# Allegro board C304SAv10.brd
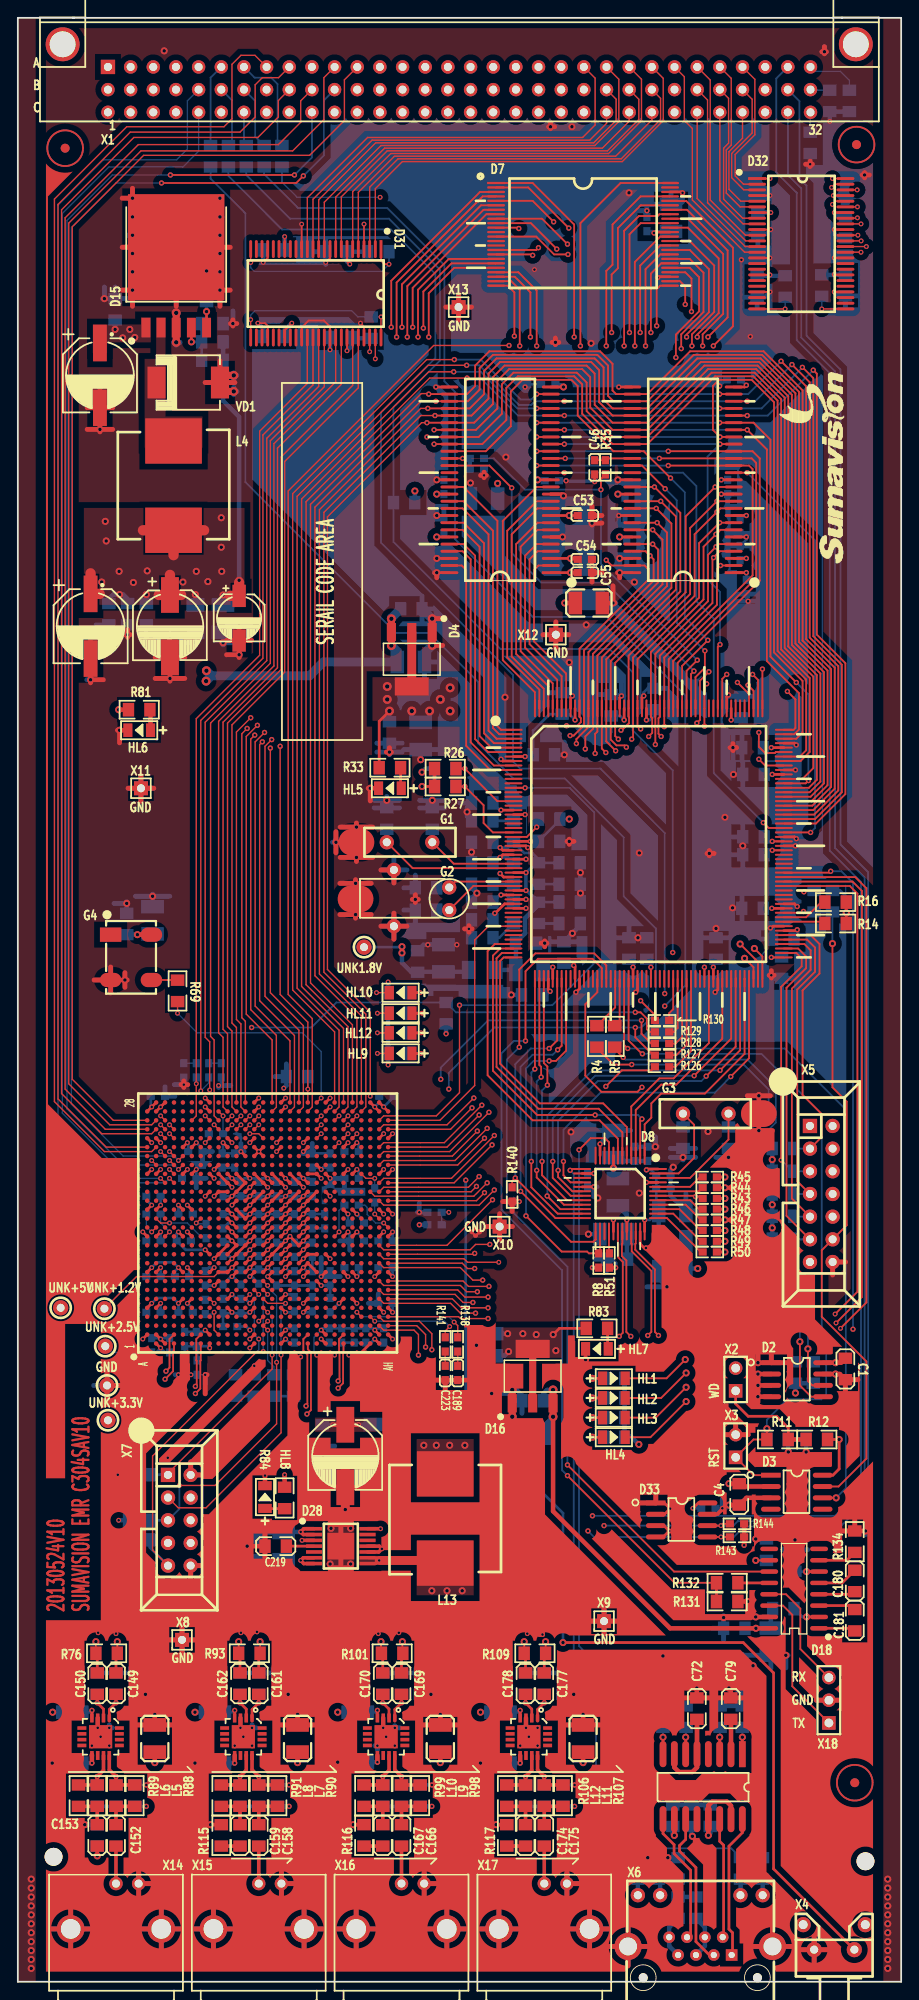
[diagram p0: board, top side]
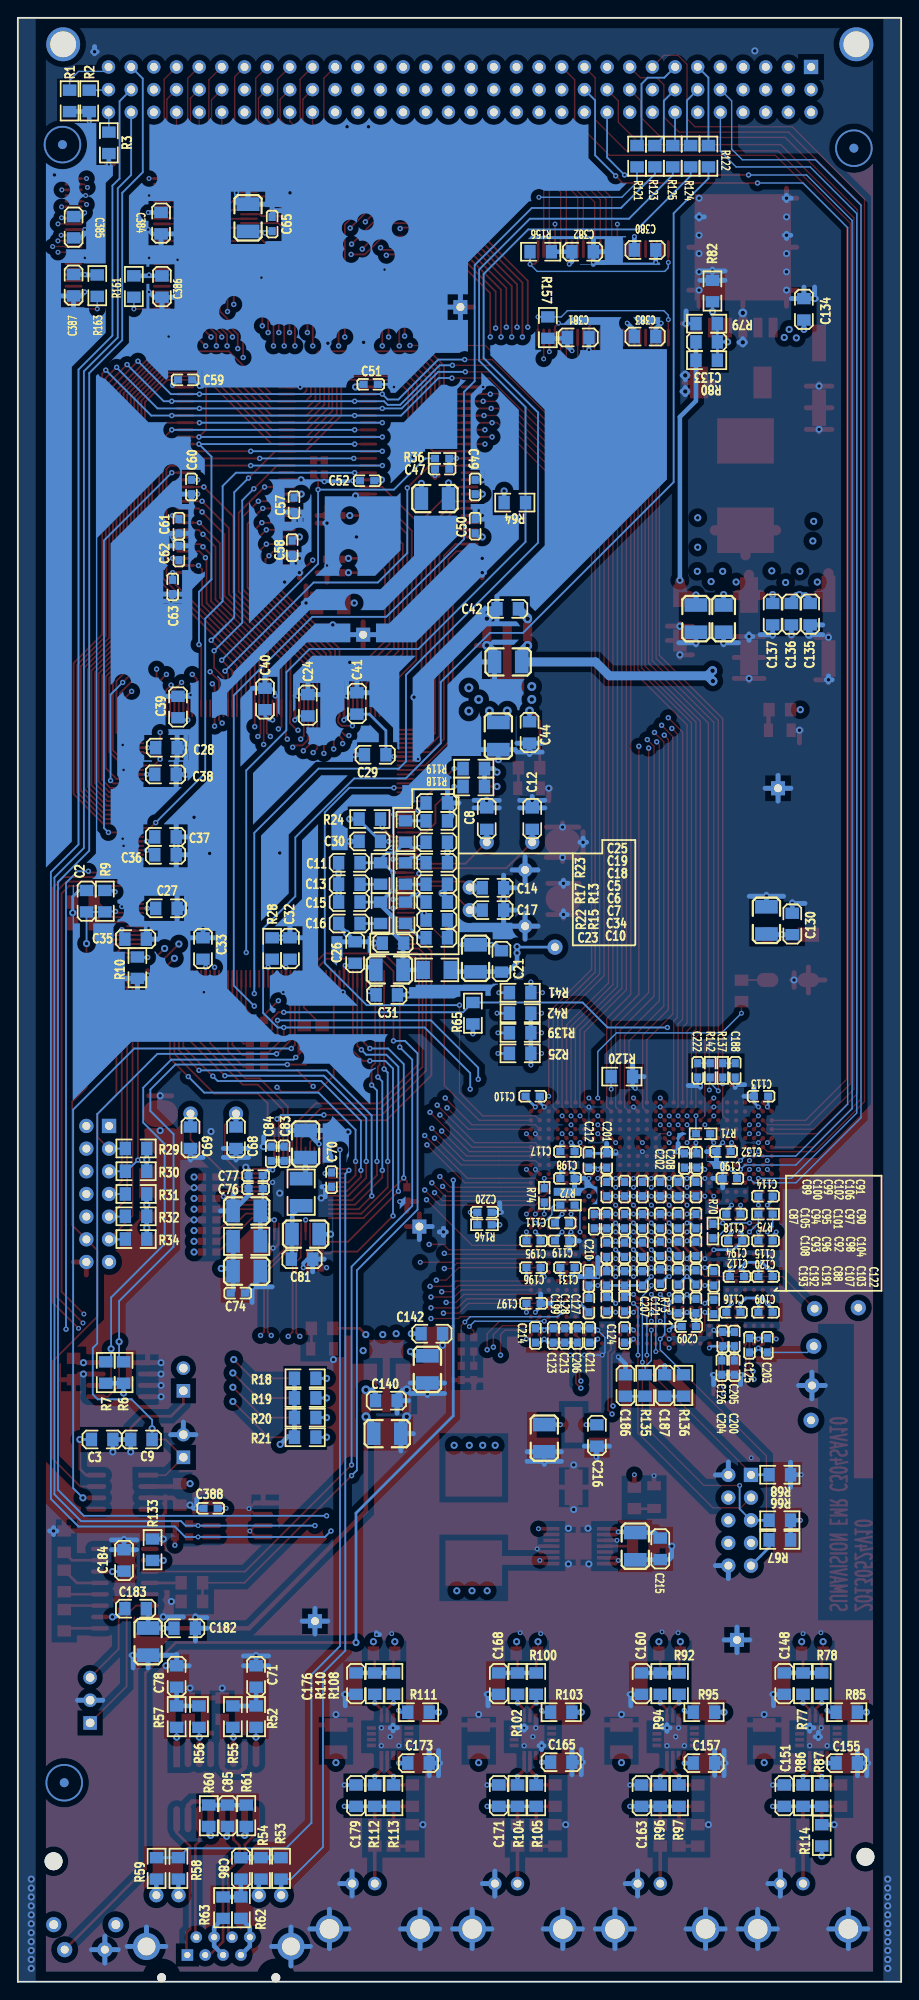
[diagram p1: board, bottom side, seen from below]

Outline 99 x 220 mm; copper layers: TOP, GND1, MIDLAYER, VCC, GND2, BOTTOM. Coordinates in mm from the lower left corner of the outline.
Outline path: 0,220 99,220 99,0 0,0 0,220

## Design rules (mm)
net group DP1: nets ASI_OUTN1 ASI_OUTP1
net group DP2: nets ASI_OUTN2 ASI_OUTP2
net group DP3: nets ASI_OUTN3 ASI_OUTP3
net group DP4: nets ASI_OUTN4 ASI_OUTP4
net group DP5: nets ENETRX+ ENETRX-
net group DP6: nets ENETTX+ ENETTX-

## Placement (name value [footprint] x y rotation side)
C1  0.1uF  [C0805]  92.75 68.65 270 top
C2  0.1uF  [C0805]  91.3 121.05 90 bottom
C3  0.1uF  [C0805]  89.55 60.75 180 bottom
C4  0.1uF  [C0805]  80.85 54.6 270 top
C5  1nF  [C0805]  52.05 125.35 0 bottom
C6  0.01uF  [C0805]  52.05 122.95 0 bottom
C7  0.1uF  [C0805]  52.05 120.95 0 bottom
C8  10pF  [C0805]  46.45 130.3 90 bottom
C9  0.1uF  [C0805]  85.15 60.75 0 bottom
C10  0.1uF  [C0805]  52.05 116.95 0 bottom
C11  0.1uF  [C0805]  61.85 125.35 180 bottom
C12  10pF  [C0805]  41.35 130.3 270 bottom
C13  0.1uF  [C0805]  61.85 122.95 180 bottom
C14  10pF  [C0805]  45.75 122.55 180 bottom
C15  0.1uF  [C0805]  61.85 120.95 180 bottom
C16  0.1uF  [C0805]  61.85 118.55 180 bottom
C17  10pF  [C0805]  45.75 120.05 0 bottom
C18  1nF  [C0805]  52.05 127.65 0 bottom
C19  0.01uF  [C0805]  52.05 130.05 0 bottom
C20  22uF/16V  [C1210]  47.7 114.65 90 bottom
C21  0.1uF  [C0805]  44.8 114.3 90 bottom
C22  22uF/16V  [C1210]  57.35 113.35 0 bottom
C23  0.1uF  [C0805]  56.95 116.35 0 bottom
C24  0.1uF  [C0805]  66.5 143 90 bottom
C25  0.1uF  [C0805]  52.05 132.05 180 bottom
C26  0.1uF  [C0805]  61.2 115.3 90 bottom
C27  0.1uF  [C0805]  82.35 120.25 180 bottom
C28  0.1uF  [C0805]  82.35 138.25 180 bottom
C29  0.1uF  [C0805]  58.95 137.45 0 bottom
C30  0.1uF  [C0805]  59.55 127.75 0 bottom
C31  0.1uF  [C0805]  57.65 110.55 180 bottom
C32  0.1uF  [C0805]  68.5 115.75 90 bottom
C33  0.1uF  [C0805]  78.25 115.75 90 bottom
C34  0.1uF  [C0805]  52.05 118.95 180 bottom
C35  0.1uF  [C0805]  85.8 116.8 180 bottom
C36  0.1uF  [C0805]  82.45 126.25 180 bottom
C37  0.1uF  [C0805]  82.45 128.25 180 bottom
C38  0.1uF  [C0805]  82.45 135.25 180 bottom
C39  0.1uF  [C0805]  81.05 142.8 90 bottom
C40  0.1uF  [C0805]  71.3 143.7 90 bottom
C41  0.1uF  [C0805]  61 143.2 90 bottom
C42  0.1uF  [C0805]  44.1 153.8 0 bottom
C43  22uF/16V  [C1210]  44.05 147.85 0 bottom
C44  0.1uF  [C0805]  41.65 139.95 270 bottom
C45  22uF/16V  [C1210]  45.15 139.55 270 bottom
C46  10pF  [C0603]  64.65 169.65 270 top
C47  10pF  [C0603]  51.45 169.45 0 bottom
C48  22uF/16V  [C1210]  52.25 166.15 180 bottom
C49  0.1uF  [C0603]  47.75 167.45 90 bottom
C50  0.1uF  [C0603]  47.75 163.05 90 bottom
C51  0.1uF  [C0603]  59.45 178.95 180 bottom
C52  0.1uF  [C0603]  59.85 168.15 0 bottom
C53  0.1uF  [C0603]  63.55 164.25 0 top
C54  0.1uF  [C0603]  63.55 159.35 0 top
C55  0.1uF  [C0603]  63.55 157.85 0 top
C56  22uF/16V  [C1210]  64 154.45 0 top
C57  0.1uF  [C0603]  68.05 165.45 270 bottom
C58  0.1uF  [C0603]  68.25 160.65 270 bottom
C59  0.1uF  [C0603]  80.25 179.45 180 bottom
C60  0.1uF  [C0603]  79.55 167.45 270 bottom
C61  0.1uF  [C0603]  80.95 163.05 270 bottom
C62  0.1uF  [C0603]  80.95 160.05 90 bottom
C63  0.1uF  [C0603]  81.65 156.25 270 bottom
C64  22uF/16V  [C1210]  73.2 197.6 90 bottom
C65  0.1uF  [C0603]  70.5 196.9 90 bottom
C68  20pF  [C0805]  74.55 94.55 270 bottom
C69  20pF  [C0805]  79.65 94.55 270 bottom
C70  0.1uF  [C0603]  63.85 89.85 270 bottom
C71  0.1uF  [C0805]  72.3 34.2 270 bottom
C72  0.1uF  [C0805]  76.1 30.6 270 top
C73  22uF/16V  [C1210]  73.35 79.6 180 bottom
C74  0.1uF  [C0603]  74.35 77.15 180 bottom
C75  22uF/16V  [C1210]  73.35 86.35 0 bottom
C76  0.1uF  [C0603]  72.35 88.85 0 bottom
C77  0.01uF  [C0603]  72.35 90.3 0 bottom
C78  0.1uF  [C0805]  81.2 34.2 270 bottom
C79  NP/0.1uF  [C0805]  79.9 30.6 270 top
C80  22uF/16V  [C1210]  66.75 83.75 180 bottom
C81  0.1uF  [C0805]  67.15 80.95 180 bottom
C82  22uF/16V  [C1210]  66.75 93.85 90 bottom
C83  0.1uF  [C0603]  69.15 92.75 90 bottom
C84  0.01uF  [C0603]  70.6 92.75 90 bottom
C85  0.1uF  [C0805]  75.5 18.6 270 bottom
C86  0.1uF  [C0805]  74 12.7 90 bottom
C87  0.1uF  [C0603]  34.4 85.2 270 bottom
C88  0.1uF  [C0603]  27 79 270 bottom
C89  0.1uF  [C0603]  33 88.8 90 bottom
C90  0.1uF  [C0603]  23 85.2 90 bottom
C91  0.1uF  [C0603]  23 88.8 90 bottom
C92  0.1uF  [C0603]  27 82.1 90 bottom
C93  0.1uF  [C0603]  31 82 90 bottom
C94  0.1uF  [C0603]  31 85.2 270 bottom
C95  0.1uF  [C0603]  29 85.2 270 bottom
C96  0.1uF  [C0603]  29 82 90 bottom
C97  0.1uF  [C0603]  25 85.2 270 bottom
C98  0.1uF  [C0603]  25 82.1 90 bottom
C99  0.1uF  [C0603]  29 88.8 90 bottom
C100  0.1uF  [C0603]  31 88.8 90 bottom
C101  0.1uF  [C0603]  27 85.2 270 bottom
C102  0.1uF  [C0603]  27 88.8 90 bottom
C103  0.1uF  [C0603]  23 78.9 270 bottom
C104  0.1uF  [C0603]  23 82.1 270 bottom
C105  0.1uF  [C0603]  33 85.2 270 bottom
C106  0.1uF  [C0603]  25 88.8 90 bottom
C107  0.1uF  [C0603]  25 78.9 270 bottom
C108  0.1uF  [C0603]  33 82 90 bottom
C109  0.1uF  [C0603]  15.2 75 0 bottom
C110  0.1uF  [C0603]  41.3 99.2 180 bottom
C111  0.1uF  [C0603]  38 85 180 bottom
C112  0.1uF  [C0603]  18.4 79 0 bottom
C113  0.1uF  [C0603]  15.7 99.2 0 bottom
C114  0.1uF  [C0603]  15.2 88 0 bottom
C115  0.1uF  [C0603]  15.2 83 0 bottom
C116  0.1uF  [C0603]  18.8 75 0 bottom
C117  0.1uF  [C0603]  37.4 93 180 bottom
C118  0.1uF  [C0603]  18.8 86 0 bottom
C119  0.1uF  [C0603]  38 83 180 bottom
C120  0.1uF  [C0603]  15.2 79 0 bottom
C121  0.1uF  [C0603]  23 75.7 90 bottom
C122  0.1uF  [C0603]  21 78.8 90 bottom
C123  0.1uF  [C0603]  39 72.4 90 bottom
C124  0.1uF  [C0603]  31 72.4 90 bottom
C125  0.1uF  [C0603]  17 71.3 90 bottom
C126  0.1uF  [C0603]  20 72 90 bottom
C127  0.1uF  [C0603]  31 75.9 90 bottom
C128  0.1uF  [C0603]  33 75.9 90 bottom
C129  22uF/16V  [C1210]  15.1 118.9 90 bottom
C130  0.1uF  [C0805]  12.2 118.5 90 bottom
C131  0.1uF  [C0603]  37.4 80 180 bottom
C132  0.1uF  [C0603]  19.9 93 0 bottom
C133  0.01uF  [C0805]  21.8 183.7 0 bottom
C134  0.1uF  [C0805]  10.9 187.35 90 bottom
C135  0.01uF  [C0805]  10.2 153.2 270 bottom
C136  0.1uF  [C0805]  12.3 153.2 270 bottom
C137  1uF  [C0805]  14.4 153.2 270 bottom
C138  10uF/16V  [C1206]  19.9 152.7 270 bottom
C139  22uF/16V  [C1210]  23 152.7 270 bottom
C140  0.1uF  [C0805]  57.7 65.1 180 bottom
C141  22uF/16V  [C1210]  57.6 61.4 180 bottom
C142  0.1uF  [C0805]  52.6 72.6 180 bottom
C143  22uF/16V  [C1210]  53.1 68.6 270 bottom
C148  0.1uF  [C0805]  13.1 33.4 270 bottom
C149  1uF  [C0805]  11 33.4 270 top
C150  1uF  [C0805]  8.9 33.4 270 top
C151  0.1uF  [C0805]  13.1 20.85 90 bottom
C152  4.7uF  [C0805]  11 16.4 270 top
C153  4.7uF  [C0805]  8.9 16.4 270 top
C154  22uF/16V  [C1210]  15.35 27.25 90 top
C155  0.1uF  [C0805]  6.1 24.5 180 bottom
C156  22uF/16V  [C1210]  31.35 27.25 90 top
C157  0.1uF  [C0805]  22.1 24.5 180 bottom
C158  4.7uF  [C0805]  27 16.4 270 top
C159  4.7uF  [C0805]  24.9 16.4 270 top
C160  0.1uF  [C0805]  29.1 33.4 270 bottom
C161  1uF  [C0805]  27 33.4 270 top
C162  1uF  [C0805]  24.9 33.4 270 top
C163  0.1uF  [C0805]  29.1 20.85 90 bottom
C164  22uF/16V  [C1210]  47.35 27.25 90 top
C165  0.1uF  [C0805]  38.1 24.6 180 bottom
C166  4.7uF  [C0805]  43 16.4 270 top
C167  4.7uF  [C0805]  40.9 16.4 270 top
C168  0.1uF  [C0805]  45.1 33.4 270 bottom
C169  1uF  [C0805]  43 33.4 270 top
C170  1uF  [C0805]  40.9 33.4 270 top
C171  0.1uF  [C0805]  45.1 20.85 90 bottom
C172  22uF/16V  [C1210]  63.35 27.25 90 top
C173  0.1uF  [C0805]  54.1 24.5 180 bottom
C174  4.7uF  [C0805]  56.9 16.4 270 top
C175  4.7uF  [C0805]  59 16.4 270 top
C176  0.1uF  [C0805]  61.1 33.4 270 bottom
C177  1uF  [C0805]  59 33.4 270 top
C178  1uF  [C0805]  56.9 33.4 270 top
C179  0.1uF  [C0805]  61.1 20.85 90 bottom
C180  0.1uF  [C0805]  93.8 44.9 270 top
C181  0.1uF  [C0805]  93.8 40.5 270 top
C182  0.1uF  [C0805]  80.3 39.6 180 bottom
C183  0.1uF  [C0805]  85.8 41.8 180 bottom
C184  0.1uF  [C0805]  87.1 47.2 90 bottom
C185  22uF/16V  [C1210]  84.4 38.1 270 bottom
C186  10pF  [C0805]  30.9 66.8 90 bottom
C187  10pF  [C0805]  26.5 66.8 90 bottom
C188  10pF  [C0603]  18.6 102.1 270 bottom
C189  10pF  [C0603]  49.3 68.2 270 top
C190  0.1uF  [C0603]  19.2 90 0 bottom
C191  0.1uF  [C0603]  29 78.8 270 bottom
C192  0.1uF  [C0603]  31 78.8 270 bottom
C193  0.1uF  [C0603]  33 78.8 270 bottom
C194  0.1uF  [C0603]  18.6 83 0 bottom
C195  0.1uF  [C0603]  41.2 83 180 bottom
C196  0.1uF  [C0603]  41.2 80 180 bottom
C197  0.1uF  [C0603]  41.2 76 180 bottom
C198  0.1uF  [C0603]  37.4 90 180 bottom
C199  0.1uF  [C0603]  35 75.8 270 bottom
C200  0.1uF  [C0603]  18.7 68.8 270 bottom
C201  0.1uF  [C0603]  33 92 90 bottom
C202  0.1uF  [C0603]  24.3 92 90 bottom
C203  0.1uF  [C0603]  15 71.3 90 bottom
C204  0.1uF  [C0603]  20.1 68.8 270 bottom
C205  0.1uF  [C0603]  18.7 72 90 bottom
C206  0.1uF  [C0603]  36.3 72.4 90 bottom
C207  0.1uF  [C0603]  25 75.7 90 bottom
C208  0.1uF  [C0603]  22.9 92 90 bottom
C209  0.1uF  [C0603]  23.8 73.4 0 bottom
C210  0.1uF  [C0603]  35 78.8 90 bottom
C211  0.1uF  [C0603]  34.9 72.4 90 bottom
C212  0.1uF  [C0603]  35 92 90 bottom
C213  0.1uF  [C0603]  37.7 72.4 90 bottom
C214  0.1uF  [C0603]  41 72.4 90 bottom
C215  0.1uF  [C0805]  27 48.5 90 bottom
C216  0.1uF  [C0805]  34.1 61.2 90 bottom
C217  22uF/16V  [C1210]  29.8 48.8 90 bottom
C218  22uF/16V  [C1210]  40 60.9 90 bottom
C219  3.3nF  [C0805]  28.9 48.8 180 top
C220  0.1uF  [C0603]  46.7 86.2 180 bottom
C222  10pF  [C0603]  22.8 102.1 270 bottom
C223  10pF  [C0603]  47.9 68.2 270 top
C380  0.1uF  [C0805]  28.7 194 180 bottom
C381  0.1uF  [C0805]  36.2 184.2 180 bottom
C382  0.1uF  [C0805]  35.7 193.8 180 bottom
C383  0.1uF  [C0805]  28.7 184.3 180 bottom
C384  0.1uF  [C0805]  82.95 197 270 bottom
C385  0.1uF  [C0805]  92.75 196.55 270 bottom
C386  0.1uF  [C0805]  82.85 189.9 270 bottom
C387  0.1uF  [C0805]  92.75 190.05 270 bottom
C388  0.1uF  [C0603]  77.4 53.04 0 bottom
CE1  470uF/16V  [CAP_SMT_F]  9.2 179.95 270 top
CE2  470uF/16V  [CAP_SMT_F]  8.15 151.85 270 top
CE3  100uF/25V  [CAP_SMT_E]  17.05 155.35 0 top
CE4  22uF/16V  [CAP_SMT_B]  24.8 155.25 0 top
CE11  100uF/25V  [CAP_SMT_E]  36.7 62.4 0 top
D1  AT91RM9200  [PQFP208]  55.55 140.25 0 top
D2  AT24C16  [SOIC8]  84.45 69.35 0 top
D3  MAX706  [SOIC8]  84.4 56.75 0 top
D4  LD1117-1.8  [SOT223]  44.15 151.2 180 top
D5  HY57V641620  [TSOPII_54]  74.55 168.25 180 top
D6  HY57V641620  [TSOPII_54]  54.05 168.25 180 top
D7  SST39VF800A  [TSOP48]  63.35 195.75 0 top
D8  RTL8201BL  [LQFP48]  67.5 88.3 270 top
D9  EP3C55_780P  [FBGA780]  28 85 90 top
D11  LMH0001  [SQB16A]  10.25 29.45 270 top
D12  LMH0001  [SQB16A]  26.25 29.45 270 top
D13  LMH0001  [SQB16A]  42.25 29.45 270 top
D14  LMH0001  [SQB16A]  58.25 29.45 270 top
D15  LM2596  [TO263-5]  17.75 185.3 0 top
D16  LD1117-1.2  [SOT223]  57.7 64.8 0 top
D18  MAX202  [SOIC16]  89.8 39.6 90 top
D28  LM2853MH-1.2v  [ETSSOP14_CP]  36.2 48.8 0 top
D31  LCX16245  [SSOP48]  40.7 194.1 270 top
D32  LCX16245  [SSOP48]  82.85 202 0 top
D33  X24C04  [SOIC8]  71.5 53.64 0 top
G1  12M  [XTAL-1]  46.45 127.65 180 top
G2  32.768KHz  [XTAL-2]  48.35 120.05 90 top
G3  25M  [XTAL-1]  74.55 97.25 0 top
G4  27M/3.3V  [OSC_SMD5X7]  10.4 117.3 270 top
GND  T POINT R  [TESTPOINT]  10 66.8 0 top
HL1  LED  [LED0805]  66.8 67.6 0 top
HL2  LED  [LED0805]  66.8 65.4 0 top
HL3  LED  [LED0805]  66.8 63.2 0 top
HL4  LED  [LED0805]  66.8 61 0 top
HL5  LED  [LED0805]  41.7 133.7 180 top
HL6  LED  [LED0805]  13.6 140.2 180 top
HL7  LED  [LED0805]  64.9 70.9 180 top
HL8  LED  [LED0805]  27.7 54.3 90 top
HL9  LED  [LED0805]  42.9 104 180 top
HL10  LED  [LED0805]  42.9 110.8 180 top
HL11  LED  [LED0805]  42.9 108.5 180 top
HL12  LED  [LED0805]  42.9 106.3 180 top
HOLE1  HOLE  [HOLE2000M]  4 14 0 top
HOLE2  HOLE  [HOLE2000M]  95 13.5 0 top
L1  33uH  [1206]  52.05 113.35 0 bottom
L2  1uH  [1210]  73.35 82.95 180 bottom
L3  1uH  [1210]  67.25 88.45 90 bottom
L4  47uH  [SM_IND_12X12]  17.45 163.1 0 top
L5  5.6nH  [0805]  11 20.85 270 top
L6  5.6nH  [0805]  8.9 20.85 270 top
L7  5.6nH  [0805]  27 20.85 270 top
L8  5.6nH  [0805]  24.9 20.85 270 top
L9  5.6nH  [0805]  43 20.85 270 top
L10  5.6nH  [0805]  40.9 20.85 270 top
L11  5.6nH  [0805]  59 20.85 270 top
L12  5.6nH  [0805]  56.9 20.85 270 top
L13  4.7uH  [SM_IND_12X12]  47.9 56.4 180 top
M1  -  [MARK]  93.8 22.3 0 top
M2  -  [MARK]  93.8 22.3 180 bottom
M3  -  [MARK]  94 205.8 0 top
M4  -  [MARK]  94 205.8 180 bottom
M5  -  [MARK]  5.3 205.4 0 top
M6  -  [MARK]  5.3 205.4 180 bottom
R1  1K/NP  [0805]  93.2 210.7 270 bottom
R2  1K/NP  [0805]  91 210.7 270 bottom
R3  1K/NP  [0805]  88.8 206 270 bottom
R4  33R  [0805]  64.9 105.9 270 top
R5  33R  [0805]  66.9 105.9 270 top
R6  4.7K  [0805]  87.15 68.25 270 bottom
R7  4.7K  [0805]  89.15 68.25 270 bottom
R8  4.7K  [0603]  65.1 80.8 90 top
R9  4.7K  [0805]  89.25 121.05 270 bottom
R10  4.7K  [0805]  85.6 113.6 90 bottom
R11  1K  [0805]  85.15 60.75 0 top
R12  1K  [0805]  89.55 60.75 0 top
R13  1K  [0805]  55.55 124.15 90 bottom
R14  4.7K  [0805]  91.65 118.55 180 top
R15  10R  [0805]  55.55 119.75 90 bottom
R16  4.7K  [0805]  91.65 120.95 180 top
R17  10R  [0805]  58.35 124.15 90 bottom
R18  180R  [0805]  66.8 67.6 180 bottom
R19  180R  [0805]  66.8 65.4 180 bottom
R20  180R  [0805]  66.8 63.2 180 bottom
R21  180R  [0805]  66.8 61 180 bottom
R22  10R  [0805]  58.35 119.75 90 bottom
R23  1K  [0805]  55.55 128.85 270 bottom
R24  4.7K  [0805]  59.55 130.25 180 bottom
R25  180R  [0805]  42.7 104 0 bottom
R26  33R  [0805]  47.9 135.9 0 top
R27  33R  [0805]  47.9 133.9 0 top
R28  4.7K  [0805]  70.5 115.75 270 bottom
R29  4.7K  [0805]  85.75 93.35 180 bottom
R30  4.7K  [0805]  85.75 90.8 180 bottom
R31  4.7K  [0805]  85.75 88.25 180 bottom
R32  4.7K  [0805]  85.75 85.75 180 bottom
R33  100R  [0805]  41.7 136 0 top
R34  4.7K  [0805]  85.75 83.2 180 bottom
R35  33R  [0603]  65.85 169.65 270 top
R36  33R  [0603]  51.45 170.65 0 bottom
R41  180R  [0805]  42.7 110.8 0 bottom
R42  180R  [0805]  42.7 108.5 0 bottom
R43  4.7K  [0603]  77.55 87.75 180 top
R44  4.7K  [0603]  77.55 88.95 0 top
R45  4.7K  [0603]  77.55 90.15 0 top
R46  4.7K  [0603]  77.55 86.55 0 top
R47  4.7K  [0603]  77.55 85.35 0 top
R48  4.7K  [0603]  77.55 84.15 0 top
R49  4.7K  [0603]  77.55 82.95 0 top
R50  4.7K  [0603]  77.55 81.75 0 top
R51  5.9K  [0603]  66.3 80.8 270 top
R52  49.9R,1%  [0805]  72.3 29.7 270 bottom
R53  4.7K  [0805]  69.5 12.7 90 bottom
R54  510R  [0805]  71.75 12.7 270 bottom
R55  49.9R,1%  [0805]  74.9 29.7 270 bottom
R56  49.9R,1%  [0805]  78.7 29.7 270 bottom
R57  49.9R,1%  [0805]  81.2 29.7 270 bottom
R58  4.7K  [0805]  81 12.7 90 bottom
R59  510R  [0805]  83.45 12.7 270 bottom
R60  75R,1%  [0805]  77.6 18.6 90 bottom
R61  75R,1%  [0805]  73.4 18.6 90 bottom
R62  75R,1%  [0805]  74 8.3 90 bottom
R63  75R,1%  [0805]  76 8.3 90 bottom
R64  10K  [0805]  43.3 165.7 0 bottom
R65  10K  [0805]  48 108.5 270 bottom
R66  10K  [0805]  13.6 51.7 180 bottom
R67  10K  [0805]  13.6 49.5 180 bottom
R68  1K  [0805]  13.6 56.8 180 bottom
R69  33R  [0805]  17.9 111 270 top
R70  33R  [0603]  21.1 84.1 90 bottom
R71  33R  [0603]  22.2 95 0 bottom
R72  33R  [0603]  37.4 87 0 bottom
R73  33R  [0603]  21 75.6 90 bottom
R74  33R  [0603]  40 88.1 270 bottom
R75  33R  [0603]  15.2 86 180 bottom
R76  100R,1%  [0805]  9.95 36.8 180 top
R77  49.9R,1%  [0805]  11 33.4 270 bottom
R78  49.9R,1%  [0805]  8.9 33.4 90 bottom
R79  1K  [0805]  21.8 185.75 0 bottom
R80  1.69K,1%  [0805]  21.8 181.65 180 bottom
R81  1K  [0805]  13.6 142.5 0 top
R82  0R  [0805]  21.15 189.4 90 bottom
R83  75R  [0805]  64.9 73.2 0 top
R84  0R  [0805]  29.9 54.2 270 top
R85  750R,1%  [0805]  6.1 30.2 180 bottom
R86  75R,1%  [0805]  11 20.85 90 bottom
R87  75R,1%  [0805]  8.9 20.85 90 bottom
R88  75R,1%  [0805]  13.1 20.85 270 top
R89  75R,1%  [0805]  6.8 20.85 270 top
R90  75R,1%  [0805]  29.1 20.85 270 top
R91  75R,1%  [0805]  22.8 20.85 270 top
R92  49.9R,1%  [0805]  24.9 33.4 90 bottom
R93  100R,1%  [0805]  25.95 36.8 180 top
R94  49.9R,1%  [0805]  27 33.4 270 bottom
R95  750R,1%  [0805]  22.1 30.2 180 bottom
R96  75R,1%  [0805]  27 20.85 90 bottom
R97  75R,1%  [0805]  24.9 20.85 90 bottom
R98  75R,1%  [0805]  45.1 20.85 270 top
R99  75R,1%  [0805]  38.8 20.85 270 top
R100  49.9R,1%  [0805]  40.9 33.4 90 bottom
R101  100R,1%  [0805]  41.95 36.8 180 top
R102  49.9R,1%  [0805]  43 33.4 270 bottom
R103  750R,1%  [0805]  38.1 30.2 180 bottom
R104  75R,1%  [0805]  43 20.85 90 bottom
R105  75R,1%  [0805]  40.9 20.85 90 bottom
R106  75R,1%  [0805]  54.8 20.85 270 top
R107  75R,1%  [0805]  61.1 20.85 270 top
R108  49.9R,1%  [0805]  56.9 33.4 90 bottom
R109  100R,1%  [0805]  57.95 36.8 180 top
R110  49.9R,1%  [0805]  59 33.4 270 bottom
R111  750R,1%  [0805]  54.1 30.2 180 bottom
R112  75R,1%  [0805]  59 20.85 90 bottom
R113  75R,1%  [0805]  56.9 20.85 90 bottom
R114  75R,1%  [0805]  8.9 16.4 90 bottom
R115  75R,1%  [0805]  22.8 16.4 90 top
R116  75R,1%  [0805]  38.8 16.4 90 top
R117  75R,1%  [0805]  54.8 16.4 90 top
R118  4.7K  [0805]  47.9 133.9 0 bottom
R119  4.7K  [0805]  47.9 135.9 0 bottom
R120  4.7K  [0805]  31.3 101.4 180 bottom
R121  0R  [0805]  29.6 204.5 270 bottom
R122  0R  [0805]  21.6 204.5 270 bottom
R123  0R  [0805]  27.6 204.5 270 bottom
R124  0R  [0805]  23.6 204.5 270 bottom
R125  0R  [0805]  25.6 204.5 270 bottom
R126  0R/NP  [0603]  72.2 102.5 0 top
R127  0R/NP  [0603]  72.2 103.8 0 top
R128  0R/NP  [0603]  72.2 105.1 0 top
R129  0R/NP  [0603]  72.2 106.4 0 top
R130  0R/NP  [0603]  72.2 107.7 0 top
R131  10K  [0805]  79.5 42.6 180 top
R132  4.7K  [0805]  79.5 44.7 0 top
R133  4.7K  [0805]  83.9 48.4 270 bottom
R134  4.7K  [0805]  93.8 49.3 90 top
R135  33R  [0805]  28.7 66.8 270 bottom
R136  33R  [0805]  24.4 66.8 270 bottom
R137  33R  [0603]  20 102.1 90 bottom
R138  33R  [0603]  49.3 71.4 270 top
R139  180R  [0805]  42.7 106.3 0 bottom
R140  4.7K  [0603]  55.4 88.2 90 top
R141  1K  [0603]  47.9 71.4 270 top
R142  1K  [0603]  21.4 102.1 90 bottom
R143  4.7K  [0603]  80.6 49.83 180 top
R144  4.7K  [0603]  80.6 51.3 180 top
R146  4.7K  [0603]  46.7 84.8 180 bottom
R156  4.7K  [0805]  40.4 193.8 0 bottom
R157  4.7K  [0805]  39.6 185.3 270 bottom
R161  4.7K  [0805]  86 189.9 270 bottom
R163  4.7K  [0805]  90.1 190 90 bottom
T1  -  [H1102]  81.2 25.5 180 top
UNK1.8V  T POINT R  [TESTPOINT]  38.8 115.9 0 top
UNK+1.2V  T POINT R  [TESTPOINT]  9.7 75.4 0 top
UNK+2.5V  T POINT R  [TESTPOINT]  9.8 71.2 0 top
UNK+3.3V  T POINT R  [TESTPOINT]  10.1 62.9 0 top
UNK+5V  T POINT R  [TESTPOINT]  4.8 75.5 0 top
VD1  1N5824  [DIODE_T]  19.1 179.15 0 top
X1  CON96  [CON96_32X3_RF]  10.1 214.5 0 top
X2  CON2  [SIP2]  80.45 66.2 90 top
X3  CON2  [SIP2]  80.45 58.75 90 top
X4  SW2P  [SW2]  91.5 5 0 top
X5  CON14  [IDC14]  90.05 88.25 270 top
X6  RJ-45  [RJ45LED]  80 3 0 top
X7  -  [IDC10]  18.1 51.7 270 top
X8  GND  [SIP1]  18.4 38.3 0 top
X9  GND  [SIP1]  65.7 40.4 0 top
X10  GND  [SIP1]  54 84.6 0 top
X11  GND  [SIP1]  13.8 133.7 0 top
X12  GND  [SIP1]  60.3 150.9 0 top
X13  GND  [SIP1]  49.4 187.6 0 top
X14  -  [BNC]  11 11 0 top
X15  -  [BNC]  27 11 0 top
X16  -  [BNC]  43 11 0 top
X17  -  [BNC]  59 11 0 top
X18  CON3  [SIP3]  90.9 29 90 top

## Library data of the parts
C1-C65 C68-C143 C148-C220 C222 C223 C380-C387 = CAP NP
C388 = CAPACITOR NON-POL
CE1 CE2 = CAP POL: User Part Number: partnum; Tolerance: RichardLC
CE3 CE4 CE11 = CAP POL
D1 = AT91RM9200
D2 = AT24C16
D3 = MAX706
D4 D16 = LD1117
D5 D6 = HY57V641620
D7 = SST39VF800A_0
D8 = RTL8201BL
D9 = EP3C55_780P
D11-D14 = LMH0001
D15 = LM2596
D18 = MAX202
D28 = LM2853MH
D31 D32 = LCX16245
D33 = X24C04
G1 G3 = XTAL-1
G2 = XTAL-2
G4 = OSC_SMD
GND UNK1.8V UNK+1.2V UNK+2.5V UNK+3.3V UNK+5V = T POINT R
HL1-HL12 = LED
HOLE1 HOLE2 = HOLE
L1-L13 = INDUCTOR
M1-M6 = MARK
R1-R36 R41-R142 R156 R157 R161 R163 = RES1
R143 R144 R146 = RESISTOR
T1 = H1102
VD1 = DIODE SCHOTTKY
X1 = CON96
X2 X3 = CON2
X4 = SW2P
X5 = CON14
X6 = RJ-45
X7 = IDC10
X8-X13 = CON1
X14-X17 = BNC
X18 = CON3

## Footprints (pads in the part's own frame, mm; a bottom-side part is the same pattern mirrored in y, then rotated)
0603
  rect 0.91x0.81 smd: 1(-0.8,0) 2(0.8,0)
0805
  rect 1.27x1.52 smd: 1(-1.2,0) 2(1.2,0)
1206
  rect 1.52x2.03 smd: 1(-1.524,0) 2(1.524,0)
1210
  rect 1.52x2.54 smd: 1(-1.524,0) 2(1.524,0)
BNC
  round 1.5 hole 0.9: 1(0,0) 2(2.54,0)
  round 3.1 hole 2.2: 3(5.08,-5.08) 4(-5.08,-5.08)
C0603
  rect 0.91x0.81 smd: 1(-0.8,0) 2(0.8,0)
C0805
  rect 1.27x1.52 smd: 1(-1.2,0) 2(1.2,0)
C1206
  rect 1.52x2.03 smd: 1(-1.524,0) 2(1.524,0)
C1210
  rect 1.52x2.54 smd: 1(-1.524,0) 2(1.524,0)
CAP_SMT_B
  rect 1.5x2.5 smd: 1(0,0) 2(0,-5)
CAP_SMT_E
  rect 2x4 smd: 1(0,0) 2(0,-7)
CAP_SMT_F
  rect 4.1x1.55 smd: 1(-3.625,0) 2(3.625,0)
CON96_32X3_RF
  round 3.8 hole 2.9: (-5.08,2.54) (83.82,2.54)
  rect 1.6x1.6 hole 0.9: A1(0,0)
  round 1.5 hole 0.9: A2(2.54,0) A3(5.08,0) A4(7.62,0) A5(10.16,0) A6(12.7,0) A7(15.24,0) A8(17.78,0) A9(20.32,0) A10(22.86,0) A11(25.4,0) A12(27.94,0) A13(30.48,0) A14(33.02,0) A15(35.56,0) A16(38.1,0) A17(40.64,0) A18(43.18,0) A19(45.72,0) A20(48.26,0) A21(50.8,0) A22(53.34,0) A23(55.88,0) A24(58.42,0) A25(60.96,0) A26(63.5,0) A27(66.04,0) A28(68.58,0) A29(71.12,0) A30(73.66,0) A31(76.2,0) A32(78.74,0) B1(0,-2.54) B2(2.54,-2.54) B3(5.08,-2.54) B4(7.62,-2.54) B5(10.16,-2.54) B6(12.7,-2.54) B7(15.24,-2.54) B8(17.78,-2.54) B9(20.32,-2.54) B10(22.86,-2.54) B11(25.4,-2.54) B12(27.94,-2.54) B13(30.48,-2.54) B14(33.02,-2.54) B15(35.56,-2.54) B16(38.1,-2.54) B17(40.64,-2.54) B18(43.18,-2.54) B19(45.72,-2.54) B20(48.26,-2.54) B21(50.8,-2.54) B22(53.34,-2.54) B23(55.88,-2.54) B24(58.42,-2.54) B25(60.96,-2.54) B26(63.5,-2.54) B27(66.04,-2.54) B28(68.58,-2.54) B29(71.12,-2.54) B30(73.66,-2.54) B31(76.2,-2.54) B32(78.74,-2.54) C1(0,-5.08) C2(2.54,-5.08) C3(5.08,-5.08) C4(7.62,-5.08) C5(10.16,-5.08) C6(12.7,-5.08) C7(15.24,-5.08) C8(17.78,-5.08) C9(20.32,-5.08) C10(22.86,-5.08) C11(25.4,-5.08) C12(27.94,-5.08) C13(30.48,-5.08) C14(33.02,-5.08) C15(35.56,-5.08) C16(38.1,-5.08) C17(40.64,-5.08) C18(43.18,-5.08) C19(45.72,-5.08) C20(48.26,-5.08) C21(50.8,-5.08) C22(53.34,-5.08) C23(55.88,-5.08) C24(58.42,-5.08) C25(60.96,-5.08) C26(63.5,-5.08) C27(66.04,-5.08) C28(68.58,-5.08) C29(71.12,-5.08) C30(73.66,-5.08) C31(76.2,-5.08) C32(78.74,-5.08)
DIODE_T
  rect 2.03x3.56 smd: 1(3.556,0) 2(-3.556,0)
ETSSOP14_CP
  rect 1.8x0.4 smd: 1(-3,1.95) 2(-3,1.3) 3(-3,0.65) 4(-3,0) 5(-3,-0.65) 6(-3,-1.3) 7(-3,-1.95) 8(3,-1.95) 9(3,-1.3) 10(3,-0.65) 11(3,0) 12(3,0.65) 13(3,1.3) 14(3,1.95)
  rect 3x3 smd: EP(0,0)
FBGA780
  round 0.5 smd: A2(-12.5,13.5) A3(-11.5,13.5) A4(-10.5,13.5) A5(-9.5,13.5) A6(-8.5,13.5) A7(-7.5,13.5) A8(-6.5,13.5) A9(-5.5,13.5) A10(-4.5,13.5) A11(-3.5,13.5) A12(-2.5,13.5) A13(-1.5,13.5) A14(-0.5,13.5) A15(0.5,13.5) A16(1.5,13.5) A17(2.5,13.5) A18(3.5,13.5) A19(4.5,13.5) A20(5.5,13.5) A21(6.5,13.5) A22(7.5,13.5) A23(8.5,13.5) A24(9.5,13.5) A25(10.5,13.5) A26(11.5,13.5) A27(12.5,13.5) AA1(-13.5,-6.5) AA2(-12.5,-6.5) AA3(-11.5,-6.5) AA4(-10.5,-6.5) AA5(-9.5,-6.5) AA6(-8.5,-6.5) AA7(-7.5,-6.5) AA8(-6.5,-6.5) AA9(-5.5,-6.5) AA10(-4.5,-6.5) AA11(-3.5,-6.5) AA12(-2.5,-6.5) AA13(-1.5,-6.5) AA14(-0.5,-6.5) AA15(0.5,-6.5) AA16(1.5,-6.5) AA17(2.5,-6.5) AA18(3.5,-6.5) AA19(4.5,-6.5) AA20(5.5,-6.5) AA21(6.5,-6.5) AA22(7.5,-6.5) AA23(8.5,-6.5) AA24(9.5,-6.5) AA25(10.5,-6.5) AA26(11.5,-6.5) AA27(12.5,-6.5) AA28(13.5,-6.5) AB1(-13.5,-7.5) AB2(-12.5,-7.5) AB3(-11.5,-7.5) AB4(-10.5,-7.5) AB5(-9.5,-7.5) AB6(-8.5,-7.5) AB7(-7.5,-7.5) AB8(-6.5,-7.5) AB9(-5.5,-7.5) AB10(-4.5,-7.5) AB11(-3.5,-7.5) AB12(-2.5,-7.5) AB13(-1.5,-7.5) AB14(-0.5,-7.5) AB15(0.5,-7.5) AB16(1.5,-7.5) AB17(2.5,-7.5) AB18(3.5,-7.5) AB19(4.5,-7.5) AB20(5.5,-7.5) AB21(6.5,-7.5) AB22(7.5,-7.5) AB23(8.5,-7.5) AB24(9.5,-7.5) AB25(10.5,-7.5) AB26(11.5,-7.5) AB27(12.5,-7.5) AB28(13.5,-7.5) AC1(-13.5,-8.5) AC2(-12.5,-8.5) AC3(-11.5,-8.5) AC4(-10.5,-8.5) AC5(-9.5,-8.5) AC6(-8.5,-8.5) AC7(-7.5,-8.5) AC8(-6.5,-8.5) AC9(-5.5,-8.5) AC10(-4.5,-8.5) AC11(-3.5,-8.5) AC12(-2.5,-8.5) AC13(-1.5,-8.5) AC14(-0.5,-8.5) AC15(0.5,-8.5) AC16(1.5,-8.5) AC17(2.5,-8.5) AC18(3.5,-8.5) AC19(4.5,-8.5) AC20(5.5,-8.5) AC21(6.5,-8.5) AC22(7.5,-8.5) AC23(8.5,-8.5) AC24(9.5,-8.5) AC25(10.5,-8.5) AC26(11.5,-8.5) AC27(12.5,-8.5) AC28(13.5,-8.5) AD1(-13.5,-9.5) AD2(-12.5,-9.5) AD3(-11.5,-9.5) AD4(-10.5,-9.5) AD5(-9.5,-9.5) AD6(-8.5,-9.5) AD7(-7.5,-9.5) AD8(-6.5,-9.5) AD9(-5.5,-9.5) AD10(-4.5,-9.5) AD11(-3.5,-9.5) AD12(-2.5,-9.5) AD13(-1.5,-9.5) AD14(-0.5,-9.5) AD15(0.5,-9.5) AD16(1.5,-9.5) AD17(2.5,-9.5) AD18(3.5,-9.5) AD19(4.5,-9.5) AD20(5.5,-9.5) AD21(6.5,-9.5) AD22(7.5,-9.5) AD23(8.5,-9.5) AD24(9.5,-9.5) AD25(10.5,-9.5) AD26(11.5,-9.5) AD27(12.5,-9.5) AD28(13.5,-9.5) AE1(-13.5,-10.5) AE2(-12.5,-10.5) AE3(-11.5,-10.5) AE4(-10.5,-10.5) AE5(-9.5,-10.5) AE6(-8.5,-10.5) AE7(-7.5,-10.5) AE8(-6.5,-10.5) AE9(-5.5,-10.5) AE10(-4.5,-10.5) AE11(-3.5,-10.5) AE12(-2.5,-10.5) AE13(-1.5,-10.5) AE14(-0.5,-10.5) AE15(0.5,-10.5) AE16(1.5,-10.5) AE17(2.5,-10.5) AE18(3.5,-10.5) AE19(4.5,-10.5) AE20(5.5,-10.5) AE21(6.5,-10.5) AE22(7.5,-10.5) AE23(8.5,-10.5) AE24(9.5,-10.5) AE25(10.5,-10.5) AE26(11.5,-10.5) AE27(12.5,-10.5) AE28(13.5,-10.5) AF1(-13.5,-11.5) AF2(-12.5,-11.5) AF3(-11.5,-11.5) AF4(-10.5,-11.5) AF5(-9.5,-11.5) AF6(-8.5,-11.5) AF7(-7.5,-11.5) AF8(-6.5,-11.5) AF9(-5.5,-11.5) AF10(-4.5,-11.5) AF11(-3.5,-11.5) AF12(-2.5,-11.5) AF13(-1.5,-11.5) AF14(-0.5,-11.5) AF15(0.5,-11.5) AF16(1.5,-11.5) AF17(2.5,-11.5) AF18(3.5,-11.5) AF19(4.5,-11.5) AF20(5.5,-11.5) AF21(6.5,-11.5) AF22(7.5,-11.5) AF23(8.5,-11.5) AF24(9.5,-11.5) AF25(10.5,-11.5) AF26(11.5,-11.5) AF27(12.5,-11.5) AF28(13.5,-11.5) AG1(-13.5,-12.5) AG2(-12.5,-12.5) AG3(-11.5,-12.5) AG4(-10.5,-12.5) AG5(-9.5,-12.5) AG6(-8.5,-12.5) AG7(-7.5,-12.5) AG8(-6.5,-12.5) AG9(-5.5,-12.5) AG10(-4.5,-12.5) AG11(-3.5,-12.5) AG12(-2.5,-12.5) AG13(-1.5,-12.5) AG14(-0.5,-12.5) AG15(0.5,-12.5) AG16(1.5,-12.5) AG17(2.5,-12.5) AG18(3.5,-12.5) AG19(4.5,-12.5) AG20(5.5,-12.5) AG21(6.5,-12.5) AG22(7.5,-12.5) AG23(8.5,-12.5) AG24(9.5,-12.5) AG25(10.5,-12.5) AG26(11.5,-12.5) AG27(12.5,-12.5) AG28(13.5,-12.5) AH2(-12.5,-13.5) AH3(-11.5,-13.5) AH4(-10.5,-13.5) AH5(-9.5,-13.5) AH6(-8.5,-13.5) AH7(-7.5,-13.5) AH8(-6.5,-13.5) AH9(-5.5,-13.5) AH10(-4.5,-13.5) AH11(-3.5,-13.5) AH12(-2.5,-13.5) AH13(-1.5,-13.5) AH14(-0.5,-13.5) AH15(0.5,-13.5) AH16(1.5,-13.5) AH17(2.5,-13.5) AH18(3.5,-13.5) AH19(4.5,-13.5) AH20(5.5,-13.5) AH21(6.5,-13.5) AH22(7.5,-13.5) AH23(8.5,-13.5) AH24(9.5,-13.5) AH25(10.5,-13.5) AH26(11.5,-13.5) AH27(12.5,-13.5) B1(-13.5,12.5) B2(-12.5,12.5) B3(-11.5,12.5) B4(-10.5,12.5) B5(-9.5,12.5) B6(-8.5,12.5) B7(-7.5,12.5) B8(-6.5,12.5) B9(-5.5,12.5) B10(-4.5,12.5) B11(-3.5,12.5) B12(-2.5,12.5) B13(-1.5,12.5) B14(-0.5,12.5) B15(0.5,12.5) B16(1.5,12.5) B17(2.5,12.5) B18(3.5,12.5) B19(4.5,12.5) B20(5.5,12.5) B21(6.5,12.5) B22(7.5,12.5) B23(8.5,12.5) B24(9.5,12.5) B25(10.5,12.5) B26(11.5,12.5) B27(12.5,12.5) B28(13.5,12.5) C1(-13.5,11.5) C2(-12.5,11.5) C3(-11.5,11.5) C4(-10.5,11.5) C5(-9.5,11.5) C6(-8.5,11.5) C7(-7.5,11.5) C8(-6.5,11.5) C9(-5.5,11.5) C10(-4.5,11.5) C11(-3.5,11.5) C12(-2.5,11.5) C13(-1.5,11.5) C14(-0.5,11.5) C15(0.5,11.5) C16(1.5,11.5) C17(2.5,11.5) C18(3.5,11.5) C19(4.5,11.5) C20(5.5,11.5) C21(6.5,11.5) C22(7.5,11.5) C23(8.5,11.5) C24(9.5,11.5) C25(10.5,11.5) C26(11.5,11.5) C27(12.5,11.5) C28(13.5,11.5) D1(-13.5,10.5) D2(-12.5,10.5) D3(-11.5,10.5) D4(-10.5,10.5) D5(-9.5,10.5) D6(-8.5,10.5) D7(-7.5,10.5) D8(-6.5,10.5) D9(-5.5,10.5) D10(-4.5,10.5) D11(-3.5,10.5) D12(-2.5,10.5) D13(-1.5,10.5) D14(-0.5,10.5) D15(0.5,10.5) D16(1.5,10.5) D17(2.5,10.5) D18(3.5,10.5) D19(4.5,10.5) D20(5.5,10.5) D21(6.5,10.5) D22(7.5,10.5) D23(8.5,10.5) D24(9.5,10.5) D25(10.5,10.5) D26(11.5,10.5) D27(12.5,10.5) D28(13.5,10.5) E1(-13.5,9.5) E2(-12.5,9.5) E3(-11.5,9.5) E4(-10.5,9.5) E5(-9.5,9.5) E6(-8.5,9.5) E7(-7.5,9.5) E8(-6.5,9.5) E9(-5.5,9.5) E10(-4.5,9.5) E11(-3.5,9.5) E12(-2.5,9.5) E13(-1.5,9.5) E14(-0.5,9.5) E15(0.5,9.5) E16(1.5,9.5) E17(2.5,9.5) E18(3.5,9.5) E19(4.5,9.5) E20(5.5,9.5) E21(6.5,9.5) E22(7.5,9.5) E23(8.5,9.5) E24(9.5,9.5) E25(10.5,9.5) E26(11.5,9.5) E27(12.5,9.5) E28(13.5,9.5) F1(-13.5,8.5) F2(-12.5,8.5) F3(-11.5,8.5) F4(-10.5,8.5) F5(-9.5,8.5) F6(-8.5,8.5) F7(-7.5,8.5) F8(-6.5,8.5) F9(-5.5,8.5) F10(-4.5,8.5) F11(-3.5,8.5) F12(-2.5,8.5) F13(-1.5,8.5) F14(-0.5,8.5) F15(0.5,8.5) F16(1.5,8.5) F17(2.5,8.5) F18(3.5,8.5) F19(4.5,8.5) F20(5.5,8.5) F21(6.5,8.5) F22(7.5,8.5) F23(8.5,8.5) F24(9.5,8.5) F25(10.5,8.5) F26(11.5,8.5) F27(12.5,8.5) F28(13.5,8.5) G1(-13.5,7.5) G2(-12.5,7.5) G3(-11.5,7.5) G4(-10.5,7.5) G5(-9.5,7.5) G6(-8.5,7.5) G7(-7.5,7.5) G8(-6.5,7.5) G9(-5.5,7.5) G10(-4.5,7.5) G11(-3.5,7.5) G12(-2.5,7.5) G13(-1.5,7.5) G14(-0.5,7.5) G15(0.5,7.5) G16(1.5,7.5) G17(2.5,7.5) G18(3.5,7.5) G19(4.5,7.5) G20(5.5,7.5) G21(6.5,7.5) G22(7.5,7.5) G23(8.5,7.5) G24(9.5,7.5) G25(10.5,7.5) G26(11.5,7.5) G27(12.5,7.5) G28(13.5,7.5) H1(-13.5,6.5) H2(-12.5,6.5) H3(-11.5,6.5) H4(-10.5,6.5) H5(-9.5,6.5) H6(-8.5,6.5) H7(-7.5,6.5) H8(-6.5,6.5) H9(-5.5,6.5) H10(-4.5,6.5) H11(-3.5,6.5) H12(-2.5,6.5) H13(-1.5,6.5) H14(-0.5,6.5) H15(0.5,6.5) H16(1.5,6.5) H17(2.5,6.5) H18(3.5,6.5) H19(4.5,6.5) H20(5.5,6.5) H21(6.5,6.5) H22(7.5,6.5) H23(8.5,6.5) H24(9.5,6.5) H25(10.5,6.5) H26(11.5,6.5) H27(12.5,6.5) H28(13.5,6.5) J1(-13.5,5.5) J2(-12.5,5.5) J3(-11.5,5.5) J4(-10.5,5.5) J5(-9.5,5.5) J6(-8.5,5.5) J7(-7.5,5.5) J8(-6.5,5.5) J9(-5.5,5.5) J10(-4.5,5.5) J11(-3.5,5.5) J12(-2.5,5.5) J13(-1.5,5.5) J14(-0.5,5.5) J15(0.5,5.5) J16(1.5,5.5) J17(2.5,5.5) J18(3.5,5.5) J19(4.5,5.5) J20(5.5,5.5) J21(6.5,5.5) J22(7.5,5.5) J23(8.5,5.5) J24(9.5,5.5) J25(10.5,5.5) J26(11.5,5.5) J27(12.5,5.5) J28(13.5,5.5) K1(-13.5,4.5) K2(-12.5,4.5) K3(-11.5,4.5) K4(-10.5,4.5) K5(-9.5,4.5) K6(-8.5,4.5) K7(-7.5,4.5) K8(-6.5,4.5) K9(-5.5,4.5) K10(-4.5,4.5) K11(-3.5,4.5) K12(-2.5,4.5) K13(-1.5,4.5) K14(-0.5,4.5) K15(0.5,4.5) K16(1.5,4.5) K17(2.5,4.5) K18(3.5,4.5) K19(4.5,4.5) K20(5.5,4.5) K21(6.5,4.5) K22(7.5,4.5) K23(8.5,4.5) K24(9.5,4.5) K25(10.5,4.5) K26(11.5,4.5) K27(12.5,4.5) K28(13.5,4.5) L1(-13.5,3.5) L2(-12.5,3.5) L3(-11.5,3.5) L4(-10.5,3.5) L5(-9.5,3.5) L6(-8.5,3.5) L7(-7.5,3.5) L8(-6.5,3.5) L9(-5.5,3.5) L10(-4.5,3.5) L11(-3.5,3.5) L12(-2.5,3.5) L13(-1.5,3.5) L14(-0.5,3.5) L15(0.5,3.5) L16(1.5,3.5) L17(2.5,3.5) L18(3.5,3.5) L19(4.5,3.5) L20(5.5,3.5) L21(6.5,3.5) L22(7.5,3.5) L23(8.5,3.5) L24(9.5,3.5) L25(10.5,3.5) L26(11.5,3.5) L27(12.5,3.5) L28(13.5,3.5) M1(-13.5,2.5) M2(-12.5,2.5) M3(-11.5,2.5) M4(-10.5,2.5) M5(-9.5,2.5) M6(-8.5,2.5) M7(-7.5,2.5) M8(-6.5,2.5) M9(-5.5,2.5) M10(-4.5,2.5) M11(-3.5,2.5) M12(-2.5,2.5) M13(-1.5,2.5) M14(-0.5,2.5) M15(0.5,2.5) M16(1.5,2.5) M17(2.5,2.5) M18(3.5,2.5) M19(4.5,2.5) M20(5.5,2.5) M21(6.5,2.5) M22(7.5,2.5) M23(8.5,2.5) M24(9.5,2.5) M25(10.5,2.5) M26(11.5,2.5) M27(12.5,2.5) M28(13.5,2.5) N1(-13.5,1.5) N2(-12.5,1.5) N3(-11.5,1.5) N4(-10.5,1.5) N5(-9.5,1.5) N6(-8.5,1.5) N7(-7.5,1.5) N8(-6.5,1.5) N9(-5.5,1.5) N10(-4.5,1.5) N11(-3.5,1.5) N12(-2.5,1.5) N13(-1.5,1.5) N14(-0.5,1.5) N15(0.5,1.5) N16(1.5,1.5) N17(2.5,1.5) N18(3.5,1.5) N19(4.5,1.5) N20(5.5,1.5) N21(6.5,1.5) N22(7.5,1.5) N23(8.5,1.5) N24(9.5,1.5) N25(10.5,1.5) N26(11.5,1.5) N27(12.5,1.5) N28(13.5,1.5) P1(-13.5,0.5) P2(-12.5,0.5) P3(-11.5,0.5) P4(-10.5,0.5) P5(-9.5,0.5) P6(-8.5,0.5) P7(-7.5,0.5) P8(-6.5,0.5) P9(-5.5,0.5) P10(-4.5,0.5) P11(-3.5,0.5) P12(-2.5,0.5) P13(-1.5,0.5) P14(-0.5,0.5) P15(0.5,0.5) P16(1.5,0.5) P17(2.5,0.5) P18(3.5,0.5) P19(4.5,0.5) P20(5.5,0.5) P21(6.5,0.5) P22(7.5,0.5) P23(8.5,0.5) P24(9.5,0.5) P25(10.5,0.5) P26(11.5,0.5) P27(12.5,0.5) P28(13.5,0.5) R1(-13.5,-0.5) R2(-12.5,-0.5) R3(-11.5,-0.5) R4(-10.5,-0.5) R5(-9.5,-0.5) R6(-8.5,-0.5) R7(-7.5,-0.5) R8(-6.5,-0.5) R9(-5.5,-0.5) R10(-4.5,-0.5) R11(-3.5,-0.5) R12(-2.5,-0.5) R13(-1.5,-0.5) R14(-0.5,-0.5) R15(0.5,-0.5) R16(1.5,-0.5) R17(2.5,-0.5) R18(3.5,-0.5) R19(4.5,-0.5) R20(5.5,-0.5) R21(6.5,-0.5) R22(7.5,-0.5) R23(8.5,-0.5) R24(9.5,-0.5) R25(10.5,-0.5) R26(11.5,-0.5) R27(12.5,-0.5) R28(13.5,-0.5) T1(-13.5,-1.5) T2(-12.5,-1.5) T3(-11.5,-1.5) T4(-10.5,-1.5) T5(-9.5,-1.5) T6(-8.5,-1.5) T7(-7.5,-1.5) T8(-6.5,-1.5) T9(-5.5,-1.5) T10(-4.5,-1.5) T11(-3.5,-1.5) T12(-2.5,-1.5) T13(-1.5,-1.5) T14(-0.5,-1.5) T15(0.5,-1.5) T16(1.5,-1.5) T17(2.5,-1.5) T18(3.5,-1.5) T19(4.5,-1.5) T20(5.5,-1.5) T21(6.5,-1.5) T22(7.5,-1.5) T23(8.5,-1.5) T24(9.5,-1.5) T25(10.5,-1.5) T26(11.5,-1.5) T27(12.5,-1.5) T28(13.5,-1.5) U1(-13.5,-2.5) U2(-12.5,-2.5) U3(-11.5,-2.5) U4(-10.5,-2.5) U5(-9.5,-2.5) U6(-8.5,-2.5) U7(-7.5,-2.5) U8(-6.5,-2.5) U9(-5.5,-2.5) U10(-4.5,-2.5) U11(-3.5,-2.5) U12(-2.5,-2.5) U13(-1.5,-2.5) U14(-0.5,-2.5) U15(0.5,-2.5) U16(1.5,-2.5) U17(2.5,-2.5) U18(3.5,-2.5) U19(4.5,-2.5) U20(5.5,-2.5) U21(6.5,-2.5) U22(7.5,-2.5) U23(8.5,-2.5) U24(9.5,-2.5) U25(10.5,-2.5) U26(11.5,-2.5) U27(12.5,-2.5) U28(13.5,-2.5) V1(-13.5,-3.5) V2(-12.5,-3.5) V3(-11.5,-3.5) V4(-10.5,-3.5) V5(-9.5,-3.5) V6(-8.5,-3.5) V7(-7.5,-3.5) V8(-6.5,-3.5) V9(-5.5,-3.5) V10(-4.5,-3.5) V11(-3.5,-3.5) V12(-2.5,-3.5) V13(-1.5,-3.5) V14(-0.5,-3.5) V15(0.5,-3.5) V16(1.5,-3.5) V17(2.5,-3.5) V18(3.5,-3.5) V19(4.5,-3.5) V20(5.5,-3.5) V21(6.5,-3.5) V22(7.5,-3.5) V23(8.5,-3.5) V24(9.5,-3.5) V25(10.5,-3.5) V26(11.5,-3.5) V27(12.5,-3.5) V28(13.5,-3.5) W1(-13.5,-4.5) W2(-12.5,-4.5) W3(-11.5,-4.5) W4(-10.5,-4.5) W5(-9.5,-4.5) W6(-8.5,-4.5) W7(-7.5,-4.5) W8(-6.5,-4.5) W9(-5.5,-4.5) W10(-4.5,-4.5) W11(-3.5,-4.5) W12(-2.5,-4.5) W13(-1.5,-4.5) W14(-0.5,-4.5) W15(0.5,-4.5) W16(1.5,-4.5) W17(2.5,-4.5) W18(3.5,-4.5) W19(4.5,-4.5) W20(5.5,-4.5) W21(6.5,-4.5) W22(7.5,-4.5) W23(8.5,-4.5) W24(9.5,-4.5) W25(10.5,-4.5) W26(11.5,-4.5) W27(12.5,-4.5) W28(13.5,-4.5) Y1(-13.5,-5.5) Y2(-12.5,-5.5) Y3(-11.5,-5.5) Y4(-10.5,-5.5) Y5(-9.5,-5.5) Y6(-8.5,-5.5) Y7(-7.5,-5.5) Y8(-6.5,-5.5) Y9(-5.5,-5.5) Y10(-4.5,-5.5) Y11(-3.5,-5.5) Y12(-2.5,-5.5) Y13(-1.5,-5.5) Y14(-0.5,-5.5) Y15(0.5,-5.5) Y16(1.5,-5.5) Y17(2.5,-5.5) Y18(3.5,-5.5) Y19(4.5,-5.5) Y20(5.5,-5.5) Y21(6.5,-5.5) Y22(7.5,-5.5) Y23(8.5,-5.5) Y24(9.5,-5.5) Y25(10.5,-5.5) Y26(11.5,-5.5) Y27(12.5,-5.5) Y28(13.5,-5.5)
H1102
  rect 0.76x2.92 smd: 1(0,0)
  oval 0.76x2.92 smd: 2(1.27,0) 3(2.54,0) 4(3.81,0) 5(5.08,0) 6(6.35,0) 7(7.62,0) 8(8.89,0) 9(8.89,7.28) 10(7.62,7.28) 11(6.35,7.28) 12(5.08,7.28) 13(3.81,7.28) 14(2.54,7.28) 15(1.27,7.28) 16(0,7.28)
HOLE2000M
  round 2 hole 2: 1(0,0)
IDC10
  rect 1.6x1.6 hole 0.9: 1(-5.08,-1.27)
  round 1.6 hole 0.9: 2(-5.08,1.27) 3(-2.54,-1.27) 4(-2.54,1.27) 5(0,-1.27) 6(0,1.27) 7(2.54,-1.27) 8(2.54,1.27) 9(5.08,-1.27) 10(5.08,1.27)
IDC14
  rect 1.6x1.6 hole 0.9: 1(-7.62,-1.27)
  round 1.6 hole 0.9: 2(-7.62,1.27) 3(-5.08,-1.27) 4(-5.08,1.27) 5(-2.54,-1.27) 6(-2.54,1.27) 7(0,-1.27) 8(0,1.27) 9(2.54,-1.27) 10(2.54,1.27) 11(5.08,-1.27) 12(5.08,1.27) 13(7.62,-1.27) 14(7.62,1.27)
LED0805
  rect 1.02x1.52 smd: 1(-1.27,0) 2(1.27,0)
LQFP48
  rect 2x0.22 smd: 1(-4.25,2.75)
  oval 2x0.22 smd: 2(-4.25,2.25) 3(-4.25,1.75) 4(-4.25,1.25) 5(-4.25,0.75) 6(-4.25,0.25) 7(-4.25,-0.25) 8(-4.25,-0.75) 9(-4.25,-1.25) 10(-4.25,-1.75) 11(-4.25,-2.25) 12(-4.25,-2.75) 25(4.25,-2.75) 26(4.25,-2.25) 27(4.25,-1.75) 28(4.25,-1.25) 29(4.25,-0.75) 30(4.25,-0.25) 31(4.25,0.25) 32(4.25,0.75) 33(4.25,1.25) 34(4.25,1.75) 35(4.25,2.25) 36(4.25,2.75)
  oval 0.22x2 smd: 13(-2.75,-4.25) 14(-2.25,-4.25) 15(-1.75,-4.25) 16(-1.25,-4.25) 17(-0.75,-4.25) 18(-0.25,-4.25) 19(0.25,-4.25) 20(0.75,-4.25) 21(1.25,-4.25) 22(1.75,-4.25) 23(2.25,-4.25) 24(2.75,-4.25) 37(2.75,4.25) 38(2.25,4.25) 39(1.75,4.25) 40(1.25,4.25) 41(0.75,4.25) 42(0.25,4.25) 43(-0.25,4.25) 44(-0.75,4.25) 45(-1.25,4.25) 46(-1.75,4.25) 47(-2.25,4.25) 48(-2.75,4.25)
MARK
  round 1 smd: 1(0,0)
OSC_SMD5X7
  rect 1.6x2.4 smd: 1(0,0)
  oval 1.6x2.4 smd: 2(5.08,0) 3(5.08,4.572) 4(0,4.572)
PQFP208
  rect 2x0.22 smd: 1(0,0)
  oval 2x0.22 smd: 2(0,-0.5) 3(0,-1) 4(0,-1.5) 5(0,-2) 6(0,-2.5) 7(0,-3) 8(0,-3.5) 9(0,-4) 10(0,-4.5) 11(0,-5) 12(0,-5.5) 13(0,-6) 14(0,-6.5) 15(0,-7) 16(0,-7.5) 17(0,-8) 18(0,-8.5) 19(0,-9) 20(0,-9.5) 21(0,-10) 22(0,-10.5) 23(0,-11) 24(0,-11.5) 25(0,-12) 26(0,-12.5) 27(0,-13) 28(0,-13.5) 29(0,-14) 30(0,-14.5) 31(0,-15) 32(0,-15.5) 33(0,-16) 34(0,-16.5) 35(0,-17) 36(0,-17.5) 37(0,-18) 38(0,-18.5) 39(0,-19) 40(0,-19.5) 41(0,-20) 42(0,-20.5) 43(0,-21) 44(0,-21.5) 45(0,-22) 46(0,-22.5) 47(0,-23) 48(0,-23.5) 49(0,-24) 50(0,-24.5) 51(0,-25) 52(0,-25.5) 105(30.3,-25.5) 106(30.3,-25) 107(30.3,-24.5) 108(30.3,-24) 109(30.3,-23.5) 110(30.3,-23) 111(30.3,-22.5) 112(30.3,-22) 113(30.3,-21.5) 114(30.3,-21) 115(30.3,-20.5) 116(30.3,-20) 117(30.3,-19.5) 118(30.3,-19) 119(30.3,-18.5) 120(30.3,-18) 121(30.3,-17.5) 122(30.3,-17) 123(30.3,-16.5) 124(30.3,-16) 125(30.3,-15.5) 126(30.3,-15) 127(30.3,-14.5) 128(30.3,-14) 129(30.3,-13.5) 130(30.3,-13) 131(30.3,-12.5) 132(30.3,-12) 133(30.3,-11.5) 134(30.3,-11) 135(30.3,-10.5) 136(30.3,-10) 137(30.3,-9.5) 138(30.3,-9) 139(30.3,-8.5) 140(30.3,-8) 141(30.3,-7.5) 142(30.3,-7) 143(30.3,-6.5) 144(30.3,-6) 145(30.3,-5.5) 146(30.3,-5) 147(30.3,-4.5) 148(30.3,-4) 149(30.3,-3.5) 150(30.3,-3) 151(30.3,-2.5) 152(30.3,-2) 153(30.3,-1.5) 154(30.3,-1) 155(30.3,-0.5) 156(30.3,0)
  oval 0.22x2 smd: 53(2.4,-27.9) 54(2.9,-27.9) 55(3.4,-27.9) 56(3.9,-27.9) 57(4.4,-27.9) 58(4.9,-27.9) 59(5.4,-27.9) 60(5.9,-27.9) 61(6.4,-27.9) 62(6.9,-27.9) 63(7.4,-27.9) 64(7.9,-27.9) 65(8.4,-27.9) 66(8.9,-27.9) 67(9.4,-27.9) 68(9.9,-27.9) 69(10.4,-27.9) 70(10.9,-27.9) 71(11.4,-27.9) 72(11.9,-27.9) 73(12.4,-27.9) 74(12.9,-27.9) 75(13.4,-27.9) 76(13.9,-27.9) 77(14.4,-27.9) 78(14.9,-27.9) 79(15.4,-27.9) 80(15.9,-27.9) 81(16.4,-27.9) 82(16.9,-27.9) 83(17.4,-27.9) 84(17.9,-27.9) 85(18.4,-27.9) 86(18.9,-27.9) 87(19.4,-27.9) 88(19.9,-27.9) 89(20.4,-27.9) 90(20.9,-27.9) 91(21.4,-27.9) 92(21.9,-27.9) 93(22.4,-27.9) 94(22.9,-27.9) 95(23.4,-27.9) 96(23.9,-27.9) 97(24.4,-27.9) 98(24.9,-27.9) 99(25.4,-27.9) 100(25.9,-27.9) 101(26.4,-27.9) 102(26.9,-27.9) 103(27.4,-27.9) 104(27.9,-27.9) 157(27.9,2.4) 158(27.4,2.4) 159(26.9,2.4) 160(26.4,2.4) 161(25.9,2.4) 162(25.4,2.4) 163(24.9,2.4) 164(24.4,2.4) 165(23.9,2.4) 166(23.4,2.4) 167(22.9,2.4) 168(22.4,2.4) 169(21.9,2.4) 170(21.4,2.4) 171(20.9,2.4) 172(20.4,2.4) 173(19.9,2.4) 174(19.4,2.4) 175(18.9,2.4) 176(18.4,2.4) 177(17.9,2.4) 178(17.4,2.4) 179(16.9,2.4) 180(16.4,2.4) 181(15.9,2.4) 182(15.4,2.4) 183(14.9,2.4) 184(14.4,2.4) 185(13.9,2.4) 186(13.4,2.4) 187(12.9,2.4) 188(12.4,2.4) 189(11.9,2.4) 190(11.4,2.4) 191(10.9,2.4) 192(10.4,2.4) 193(9.9,2.4) 194(9.4,2.4) 195(8.9,2.4) 196(8.4,2.4) 197(7.9,2.4) 198(7.4,2.4) 199(6.9,2.4) 200(6.4,2.4) 201(5.9,2.4) 202(5.4,2.4) 203(4.9,2.4) 204(4.4,2.4) 205(3.9,2.4) 206(3.4,2.4) 207(2.9,2.4) 208(2.4,2.4)
RJ45LED
  round 1 hole 3 unplated: (-9.91,-2.54) (2.89,-2.54)
  rect 1.3x1.3 hole 0.7: 1(0,0)
  round 1.3 hole 0.7: 2(-1,2) 3(-2,0) 4(-3,2) 5(-4,0) 6(-5,2) 7(-6,0) 8(-7,2)
  round 3.05 hole 2: 9(4.58,0.96) 10(-11.61,0.96)
  round 1.6 hole 0.9: 11(0.99,6.7) 12(3.48,6.7) 13(-10.51,6.7) 14(-8.01,6.7)
SIP1
  rect 1.57x1.57 hole 0.9: 1(0,0)
SIP2
  rect 1.52x1.52 hole 0.97: 1(0,0)
  round 1.52 hole 0.97: 2(2.54,0)
SIP3
  rect 1.52x1.52 hole 0.97: 1(0,0)
  round 1.52 hole 0.97: 2(2.54,0) 3(5.08,0)
SM_IND_12X12
  rect 6.35x5.08 smd: 1(0,9.5) 2(0,-0.5)
SOIC8
  rect 2.2x0.55 smd: 1(0,0)
  oval 2.2x0.55 smd: 2(0,-1.27) 3(0,-2.54) 4(0,-3.81) 5(5.8,-3.81) 6(5.8,-2.54) 7(5.8,-1.27) 8(5.8,0)
SOIC16
  oval 0.5x2 smd: 1(0,0) 2(1.27,0) 3(2.54,0) 4(3.81,0) 5(5.08,0) 6(6.35,0) 7(7.62,0) 8(8.89,0) 9(8.89,5.588) 10(7.62,5.588) 11(6.35,5.588) 12(5.08,5.588) 13(3.81,5.588) 14(2.54,5.588) 15(1.27,5.588) 16(0,5.588)
SOT223
  rect 1.02x2.03 smd: 1(-2.286,0) 2(0,0) 3(2.286,0)
  rect 3.81x2.03 smd: 4(0,6.096)
SQB16A
  oval 1x0.4 smd: 1(-0.1,0)
  rect 1x0.4 smd: 2(-0.1,-0.65) 3(-0.1,-1.3) 4(-0.1,-1.95) 9(4.1,-1.95) 10(4.1,-1.3) 11(4.1,-0.65) 12(4.1,0)
  rect 0.4x1 smd: 5(1.025,-3.075) 6(1.675,-3.075) 7(2.325,-3.075) 8(2.975,-3.075) 13(2.975,1.125) 14(2.325,1.125) 15(1.675,1.125) 16(1.025,1.125)
  rect 2.6x2.6 smd: 17(2,-0.975)
SSOP48
  rect 2x0.32 smd: 1(0,0)
  oval 2x0.32 smd: 2(0,-0.635) 3(0,-1.27) 4(0,-1.905) 5(0,-2.54) 6(0,-3.175) 7(0,-3.81) 8(0,-4.445) 9(0,-5.08) 10(0,-5.715) 11(0,-6.35) 12(0,-6.985) 13(0,-7.62) 14(0,-8.255) 15(0,-8.89) 16(0,-9.525) 17(0,-10.16) 18(0,-10.795) 19(0,-11.43) 20(0,-12.065) 21(0,-12.7) 22(0,-13.335) 23(0,-13.97) 24(0,-14.605) 25(9.906,-14.605) 26(9.906,-13.97) 27(9.906,-13.335) 28(9.906,-12.7) 29(9.906,-12.065) 30(9.906,-11.43) 31(9.906,-10.795) 32(9.906,-10.16) 33(9.906,-9.525) 34(9.906,-8.89) 35(9.906,-8.255) 36(9.906,-7.62) 37(9.906,-6.985) 38(9.906,-6.35) 39(9.906,-5.715) 40(9.906,-5.08) 41(9.906,-4.445) 42(9.906,-3.81) 43(9.906,-3.175) 44(9.906,-2.54) 45(9.906,-1.905) 46(9.906,-1.27) 47(9.906,-0.635) 48(9.906,0)
SW2
  round 1.7 hole 0.9: 1(-2.25,-1.4) 2(2.25,-1.4)
  round 1.7 hole 1: 3(-3.48,1.4) 4(3.48,1.4)
TESTPOINT
  round 1.702 hole 0.889: 1(0,0)
TO263-5
  rect 1x2.2 smd: 1(-3.4,0) 2(-1.7,0) 3(0,0) 4(1.7,0) 5(3.4,0)
  rect 10.8x11.9 smd: 6(0,9)
TSOP48
  rect 2x0.25 smd: 1(-9.75,5.75)
  oval 2x0.25 smd: 2(-9.75,5.25) 3(-9.75,4.75) 4(-9.75,4.25) 5(-9.75,3.75) 6(-9.75,3.25) 7(-9.75,2.75) 8(-9.75,2.25) 9(-9.75,1.75) 10(-9.75,1.25) 11(-9.75,0.75) 12(-9.75,0.25) 13(-9.75,-0.25) 14(-9.75,-0.75) 15(-9.75,-1.25) 16(-9.75,-1.75) 17(-9.75,-2.25) 18(-9.75,-2.75) 19(-9.75,-3.25) 20(-9.75,-3.75) 21(-9.75,-4.25) 22(-9.75,-4.75) 23(-9.75,-5.25) 24(-9.75,-5.75) 25(9.75,-5.75) 26(9.75,-5.25) 27(9.75,-4.75) 28(9.75,-4.25) 29(9.75,-3.75) 30(9.75,-3.25) 31(9.75,-2.75) 32(9.75,-2.25) 33(9.75,-1.75) 34(9.75,-1.25) 35(9.75,-0.75) 36(9.75,-0.25) 37(9.75,0.25) 38(9.75,0.75) 39(9.75,1.25) 40(9.75,1.75) 41(9.75,2.25) 42(9.75,2.75) 43(9.75,3.25) 44(9.75,3.75) 45(9.75,4.25) 46(9.75,4.75) 47(9.75,5.25) 48(9.75,5.75)
TSOPII_54
  rect 2x0.32 smd: 1(-5.68,10.4)
  oval 2x0.32 smd: 2(-5.68,9.6) 3(-5.68,8.8) 4(-5.68,8) 5(-5.68,7.2) 6(-5.68,6.4) 7(-5.68,5.6) 8(-5.68,4.8) 9(-5.68,4) 10(-5.68,3.2) 11(-5.68,2.4) 12(-5.68,1.6) 13(-5.68,0.8) 14(-5.68,0) 15(-5.68,-0.8) 16(-5.68,-1.6) 17(-5.68,-2.4) 18(-5.68,-3.2) 19(-5.68,-4) 20(-5.68,-4.8) 21(-5.68,-5.6) 22(-5.68,-6.4) 23(-5.68,-7.2) 24(-5.68,-8) 25(-5.68,-8.8) 26(-5.68,-9.6) 27(-5.68,-10.4) 28(5.68,-10.4) 29(5.68,-9.6) 30(5.68,-8.8) 31(5.68,-8) 32(5.68,-7.2) 33(5.68,-6.4) 34(5.68,-5.6) 35(5.68,-4.8) 36(5.68,-4) 37(5.68,-3.2) 38(5.68,-2.4) 39(5.68,-1.6) 40(5.68,-0.8) 41(5.68,0) 42(5.68,0.8) 43(5.68,1.6) 44(5.68,2.4) 45(5.68,3.2) 46(5.68,4) 47(5.68,4.8) 48(5.68,5.6) 49(5.68,6.4) 50(5.68,7.2) 51(5.68,8) 52(5.68,8.8) 53(5.68,9.6) 54(5.68,10.4)
XTAL-1
  round 1.6 hole 0.9: 1(0,0) 2(5.1,0)
  oval 4x3 smd: 3(8.5,0)
XTAL-2
  round 1.6 hole 0.9: 1(0,0) 2(2.54,0) 4(-1.8,6.2) 5(4.5,6.2)
  oval 3x4 smd: 3(1.25,10.5)

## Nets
+1.2VD: C87.1 C88.1 C89.1 C90.1 C91.1 C92.1 C93.1 C94.1 C95.1 C96.1 C97.1 C98.1 C99.1 C100.1 C101.1 C102.1 C103.1 C104.1 C105.1 C106.1 C107.1 C108.1 C191.1 C192.1 C193.1 C216.2 C218.2 CE11.1 D9.J9(VCCD_PLL3) D9.J20(VCCD_PLL2) D9.K9(VCCINT#K9) D9.K11(VCCINT#K11) D9.K13(VCCINT#K13) D9.K15(VCCINT#K15) D9.K17(VCCINT#K17) D9.K19(VCCINT#K19) D9.L10(VCCINT#L10) D9.L12(VCCINT#L12) D9.L14(VCCINT#L14) D9.L16(VCCINT#L16) D9.L18(VCCINT#L18) D9.L20(VCCINT#L20) D9.M9(VCCINT#M9) D9.M11(VCCINT#M11) D9.M13(VCCINT#M13) D9.M15(VCCINT#M15) D9.M17(VCCINT#M17) D9.M19(VCCINT#M19) D9.N10(VCCINT#N10) D9.N12(VCCINT#N12) D9.N14(VCCINT#N14) D9.N16(VCCINT#N16) D9.N18(VCCINT#N18) D9.N20(VCCINT#N20) D9.P9(VCCINT#P9) D9.P11(VCCINT#P11) D9.P13(VCCINT#P13) D9.P15(VCCINT#P15) D9.P17(VCCINT#P17) D9.P19(VCCINT#P19) D9.R10(VCCINT#R10) D9.R12(VCCINT#R12) D9.R14(VCCINT#R14) D9.R16(VCCINT#R16) D9.R18(VCCINT#R18) D9.R20(VCCINT#R20) D9.T9(VCCINT#T9) D9.T11(VCCINT#T11) D9.T13(VCCINT#T13) D9.T15(VCCINT#T15) D9.T17(VCCINT#T17) D9.T19(VCCINT#T19) D9.U10(VCCINT#U10) D9.U12(VCCINT#U12) D9.U14(VCCINT#U14) D9.U16(VCCINT#U16) D9.U18(VCCINT#U18) D9.U20(VCCINT#U20) D9.V9(VCCINT#V9) D9.V11(VCCINT#V11) D9.V13(VCCINT#V13) D9.V15(VCCINT#V15) D9.V17(VCCINT#V17) D9.V19(VCCINT#V19) D9.W10(VCCINT#W10) D9.W12(VCCINT#W12) D9.W14(VCCINT#W14) D9.W16(VCCINT#W16) D9.W18(VCCINT#W18) D9.W20(VCCINT#W20) D9.Y9(VCCD_PLL1) D9.Y20(VCCD_PLL4) D28.14(SNS) L13.2 R84.1 UNK+1.2V.1
+1.8VA: C11.2 C15.2 C18.2 C22.1 C23.1 D1.28(VDDPLL#28) D1.33(VDDOSC) D1.37(VDDPLL#37) L1.2 R17.2 R22.2 R23.2
+1.8VD: C20.1 C21.1 C24.1 C25.1 C26.1 C27.1 C28.1 C44.1 C45.1 D1.19(VDDCORE#19) D1.62(VDDCORE#62) D1.116(VDDCORE#116) D1.152(VDDCORE#152) D1.188(VDDCORE#188) D4.2(VOUT#2) D4.4(VOUT#4) L1.1 R33.1 UNK1.8V.1
+2.5VD: C121.1 C122.1 C123.1 C124.1 C125.1 C126.1 C127.1 C128.1 C142.1 C143.1 C199.1 C200.1 C201.1 C202.1 C203.1 C204.1 C205.1 C206.1 C207.1 C208.1 C209.1 C210.1 C211.1 C212.1 C213.1 C214.1 D9.AA1(VCCIO2#AA1) D9.AG1(VCCIO2#AG1) D9.B1(VCCIO1#B1) D9.H1(VCCIO1#H1) D9.J8(VCCA3) D9.J21(VCCA2) D9.K5(VCCIO1#K5) D9.N1(VCCIO1#N1) D9.N5(VCCIO1#N5) D9.T1(VCCIO2#T1) D9.T5(VCCIO2#T5) D9.W5(VCCIO2#W5) D9.Y8(VCCA1) D9.Y21(VCCA4) D16.2(VOUT#2) D16.4(VOUT#4) R83.1 UNK+2.5V.1
+3.3VD: C1.1 C4.1 C29.1 C30.1 C31.1 C32.1 C33.1 C34.1 C35.1 C36.1 C37.1 C38.1 C39.1 C40.1 C41.1 C48.1 C49.1 C50.1 C51.1 C52.1 C53.1 C54.1 C55.1 C56.1 C57.1 C58.1 C59.1 C60.1 C61.1 C62.1 C63.1 C64.1 C65.1 C70.1 C73.1 C74.1 C109.1 C110.1 C111.1 C112.1 C113.1 C114.1 C115.1 C116.1 C117.1 C118.1 C119.1 C120.1 C129.1 C130.1 C131.1 C132.1 C133.2 C135.1 C136.1 C137.1 C138.1 C139.1 C151.1 C154.1 C155.1 C156.1 C157.1 C163.1 C164.1 C165.1 C171.1 C172.1 C173.1 C179.1 C190.1 C194.1 C195.1 C196.1 C197.1 C198.1 C380.1 C381.1 C382.1 C383.1 C384.1 C385.1 C386.1 C387.1 C388.1 CE2.1 CE3.1 CE4.1 D1.7(VDDIOM#7) D1.26(VDDIOM#26) D1.40(VDDIOP#40) D1.56(VDDIOP#56) D1.75(VDDIOP#75) D1.93(VDDIOP#93) D1.111(VDDIOP#111) D1.129(VDDIOP#129) D1.131(VDDIOM#131) D1.146(VDDIOM#146) D1.164(VDDIOM#164) D1.183(VDDIOM#183) D1.199(VDDIOM#199) D2.8(VCC) D3.2(VCC) D5.1(VDD#1) D5.3(VDDQ#3) D5.9(VDDQ#9) D5.14(VDD#14) D5.27(VDD#27) D5.43(VDDQ#43) D5.49(VDDQ#49) D6.1(VDD#1) D6.3(VDDQ#3) D6.9(VDDQ#9) D6.14(VDD#14) D6.27(VDD#27) D6.43(VDDQ#43) D6.49(VDDQ#49) D7.37(VDD) D8.14(DVDD33#14) D9.A2(VCCIO8#A2) D9.A5(VCCIO8#A5) D9.A9(VCCIO8#A9) D9.A13(VCCIO8#A13) D9.A16(VCCIO7#A16) D9.A20(VCCIO7#A20) D9.A24(VCCIO7#A24) D9.A27(VCCIO7#A27) D9.AA11(VCCIO3#AA11) D9.AA18(VCCIO4#AA18) D9.AA28(VCCIO5#AA28) D9.AD6(VCCIO3#AD6) D9.AD9(VCCIO3#AD9) D9.AD13(VCCIO3#AD13) D9.AD16(VCCIO4#AD16) D9.AD20(VCCIO4#AD20) D9.AD23(VCCIO4#AD23) D9.AG28(VCCIO5#AG28) D9.AH2(VCCIO3#AH2) D9.AH5(VCCIO3#AH5) D9.AH9(VCCIO3#AH9) D9.AH13(VCCIO3#AH13) D9.AH16(VCCIO4#AH16) D9.AH20(VCCIO4#AH20) D9.AH24(VCCIO4#AH24) D9.AH27(VCCIO4#AH27) D9.B28(VCCIO6#B28) D9.E6(VCCIO8#E6) D9.E9(VCCIO8#E9) D9.E13(VCCIO8#E13) D9.E16(VCCIO7#E16) D9.E20(VCCIO7#E20) D9.E23(VCCIO7#E23) D9.H11(VCCIO8#H11) D9.H18(VCCIO7#H18) D9.H28(VCCIO6#H28) D9.K24(VCCIO6#K24) D9.N24(VCCIO6#N24) D9.N28(VCCIO6#N28) D9.T24(VCCIO5#T24) D9.T28(VCCIO5#T28) D9.W24(VCCIO5#W24) D11.9(VCC) D12.9(VCC) D13.9(VCC) D14.9(VCC) D31.7(VCC#7) D31.18(VCC#18) D31.31(VCC#31) D31.42(VCC#42) D32.7(VCC#7) D32.18(VCC#18) D32.31(VCC#31) D32.42(VCC#42) D33.8(VCC) G4.4(VCC) L2.1 L4.2 R6.2 R7.2 R8.1 R9.1 R18.1 R19.1 R20.1 R21.1 R24.1 R25.1 R29.2 R30.2 R31.2 R32.2 R34.2 R41.1 R42.1 R43.1 R45.2 R46.2 R48.2 R49.2 R50.2 R58.1 R64.2 R65.2 R66.2 R67.2 R80.1 R81.1 R85.2 R86.1 R87.1 R95.2 R96.1 R97.1 R103.2 R104.1 R105.1 R111.2 R112.1 R113.1 R118.1 R119.1 R139.1 R143.1 R144.1 R146.2 R156.1 R157.2 R161.1 R163.2 UNK+3.3V.1 X2.2 X5.1 X5.13 X6.11(LINK+) X7.4
+5VD: C42.1 C43.1 C134.1 C140.1 C141.1 C182.1 C183.2 C185.1 C215.2 C217.2 CE1.1 D4.3(VIN) D15.1(VIN) D16.3(VIN) D18.16(VCC) D28.1(AVIN) D28.2(EN) D28.6(PVIN#6) D28.7(PVIN#7) UNK+5V.1 X1.A1 X1.A2 X1.B1 X1.B2 X1.C1 X1.C2
